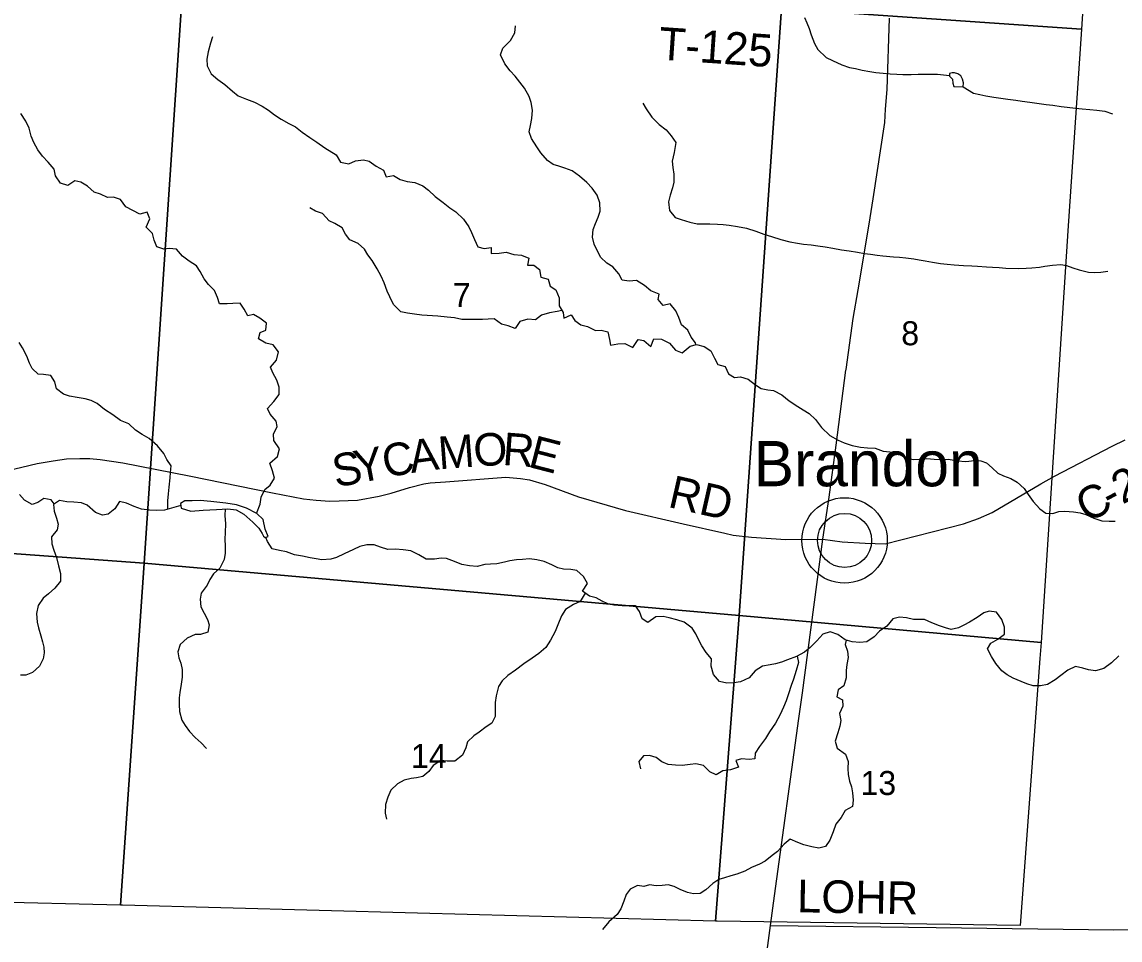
# Model space of a CAD drawing. Extents: x 1759416 to 2214760, y 252598 to 1116833.
# Drawn here: x 1958374 to 1968479, y 838519 to 846970 of the extents above; entities that cross this region are included whole.
import ezdxf

# ---------------------------------------------------------------- set-up
doc = ezdxf.new("R2010")
doc.units = 0
for name, color, linetype in [('GM_X_County_Road', 7, 'Continuous'), ('GM_X_County_Road_Text', 7, 'Continuous'), ('GM_X_Minor_Lake', 7, 'Continuous'), ('GM_X_Minor_River', 7, 'Continuous'), ('GM_X_Section', 7, 'Continuous'), ('GM_X_Section_Text', 7, 'Continuous'), ('GM_X_State_Route', 7, 'Continuous'), ('GM_X_Township_Road', 7, 'Continuous'), ('GM_X_Township_Road_Text', 7, 'Continuous'), ('GM_X_Unincorporated', 7, 'Continuous'), ('GM_X_Unincorporated_Location', 7, 'Continuous'), ('GM_X_Unincorporated_Text', 7, 'Continuous')]:
    doc.layers.add(name, color=color, linetype=linetype)

msp = doc.modelspace()

# ---------------------------------------------------------------- linework, layer by layer
at = {"layer": 'GM_X_County_Road'}
for points in [[(1965744, 842208), (1965923, 842185), (1966133, 842173), (1966317, 842167), (1967040, 842350), (1967176, 842398), (1967302, 842455), (1967751, 842718), (1967877, 842788), (1968408, 843065), (1968526, 843123)], [(1957946, 842771), (1958514, 842905), (1958662, 842931), (1958783, 842949), (1958907, 842953), (1958997, 842953), (1959095, 842943), (1959301, 842913), (1959912, 842791), (1960681, 842635), (1960964, 842579), (1961082, 842567), (1961208, 842559), (1961462, 842569), (1961661, 842605), (1961773, 842633), (1961939, 842686), (1962071, 842718), (1962129, 842726), (1962273, 842738), (1962826, 842780), (1962962, 842768), (1963046, 842754), (1963189, 842712), (1963495, 842600), (1963928, 842474), (1964459, 842349), (1964841, 842263), (1964919, 842247), (1965089, 842227), (1965404, 842205), (1965744, 842208)]]:
    msp.add_lwpolyline(points, dxfattribs=at)
at = {"layer": 'GM_X_Minor_Lake'}
for points in [[(1967034, 846372), (1967038, 846410), (1967029, 846444), (1967013, 846473), (1966987, 846491), (1966957, 846501), (1966935, 846502), (1966909, 846494), (1966909, 846470), (1966937, 846442), (1966940, 846405), (1966950, 846375)], [(1966950, 846375), (1967034, 846372)], [(1960639, 842232), (1960612, 842301), (1960593, 842389), (1960536, 842444), (1960440, 842494), (1960347, 842525), (1960251, 842540), (1960113, 842556), (1960015, 842565), (1959939, 842562), (1959873, 842561), (1959834, 842536), (1959838, 842494), (1959927, 842468), (1960042, 842475), (1960164, 842483), (1960268, 842488), (1960344, 842479), (1960415, 842440), (1960499, 842364), (1960554, 842311), (1960583, 842261)], [(1960583, 842261), (1960597, 842236), (1960611, 842223), (1960639, 842232)]]:
    msp.add_lwpolyline(points, dxfattribs=at)
at = {"layer": 'GM_X_Minor_River'}
for points in [[(1964575, 844001), (1964572, 844016), (1964531, 844069), (1964503, 844132), (1964442, 844183), (1964419, 844249), (1964392, 844312), (1964339, 844375), (1964276, 844359), (1964229, 844414), (1964238, 844464), (1964162, 844495), (1964103, 844544), (1964029, 844591), (1963963, 844584), (1963897, 844593), (1963868, 844650), (1963811, 844717), (1963757, 844751), (1963698, 844806), (1963641, 844923), (1963624, 844990), (1963631, 845058), (1963652, 845114), (1963675, 845172), (1963694, 845228), (1963691, 845304), (1963666, 845376), (1963620, 845441), (1963571, 845492), (1963506, 845549), (1963436, 845600), (1963371, 845625), (1963313, 845642), (1963261, 845659), (1963209, 845695), (1963148, 845764), (1963111, 845821), (1963064, 845896), (1963041, 845958), (1963054, 846018), (1963067, 846082), (1963072, 846157), (1963061, 846229), (1963043, 846285), (1963000, 846360), (1962914, 846470), (1962866, 846520), (1962819, 846585), (1962778, 846666), (1962799, 846730), (1962870, 846799), (1962909, 846869), (1962916, 846935)], [(1965575, 847011), (1965596, 846961), (1965618, 846909), (1965637, 846852), (1965666, 846772), (1965697, 846715), (1965776, 846642), (1965834, 846615), (1965918, 846576), (1965989, 846551), (1966045, 846540), (1966105, 846527), (1966175, 846514), (1966233, 846505), (1966299, 846498), (1966363, 846491), (1966425, 846489), (1966479, 846486), (1966557, 846485), (1966621, 846488), (1966685, 846489), (1966743, 846490), (1966799, 846488), (1966909, 846478)], [(1960126, 846832), (1960110, 846776), (1960086, 846696), (1960076, 846628), (1960077, 846566), (1960114, 846493), (1960175, 846440), (1960241, 846395), (1960312, 846332), (1960363, 846291), (1960439, 846260), (1960513, 846231), (1960584, 846194), (1960644, 846159), (1960699, 846114), (1960759, 846075), (1960830, 846034), (1960890, 846005), (1960953, 845954), (1961023, 845905), (1961086, 845862), (1961161, 845811), (1961265, 845746), (1961304, 845679), (1961382, 845664), (1961442, 845693), (1961516, 845702), (1961570, 845687), (1961632, 845642), (1961701, 845605), (1961726, 845545), (1961794, 845556), (1961854, 845521), (1961918, 845502), (1961988, 845491), (1962063, 845462), (1962115, 845423), (1962176, 845364), (1962249, 845307), (1962311, 845260), (1962368, 845223), (1962436, 845154), (1962485, 845083), (1962512, 845033), (1962537, 844966), (1962570, 844900), (1962628, 844885), (1962692, 844894), (1962692, 844838), (1962764, 844841), (1962830, 844850), (1962900, 844829), (1962972, 844824), (1963037, 844797), (1963026, 844731), (1963084, 844730), (1963138, 844690), (1963149, 844621), (1963215, 844602), (1963236, 844538), (1963287, 844503), (1963319, 844430), (1963318, 844356), (1963353, 844294), (1963360, 844243), (1963429, 844274), (1963462, 844222), (1963517, 844183), (1963579, 844168), (1963653, 844131), (1963703, 844132), (1963765, 844116), (1963782, 844047), (1963789, 843995), (1963857, 844006), (1963923, 844009), (1963995, 843974), (1964044, 844046), (1964096, 844039), (1964161, 843984), (1964190, 844052), (1964260, 844051), (1964334, 844014), (1964389, 843949), (1964451, 843924), (1964522, 843987), (1964582, 844002), (1964652, 843981), (1964713, 843942), (1964748, 843876), (1964779, 843817), (1964845, 843798), (1964876, 843732), (1964932, 843697), (1964986, 843702), (1965058, 843681), (1965125, 843630), (1965177, 843597), (1965239, 843584), (1965291, 843576), (1965366, 843538)], [(1967034, 846372), (1967129, 846315), (1967189, 846302), (1967245, 846291), (1967317, 846278), (1967448, 846260), (1967520, 846249), (1967578, 846240), (1967648, 846231), (1967714, 846222), (1967800, 846211), (1967860, 846204), (1967938, 846193), (1967992, 846187), (1968070, 846176), (1968132, 846169), (1968200, 846164), (1968264, 846157), (1968340, 846148), (1968411, 846125)], [(1964087, 846221), (1964119, 846171), (1964170, 846092), (1964237, 846025), (1964302, 845976), (1964349, 845921), (1964391, 845860), (1964377, 845768), (1964356, 845690), (1964364, 845630), (1964373, 845570), (1964374, 845495), (1964361, 845443), (1964340, 845377), (1964325, 845313), (1964334, 845233), (1964385, 845170), (1964439, 845151), (1964521, 845128), (1964589, 845113), (1964703, 845112), (1964775, 845109), (1964827, 845104), (1964881, 845099), (1964959, 845088), (1965043, 845071), (1965126, 845044), (1965200, 845015), (1965272, 844994), (1965359, 844967), (1965441, 844947), (1965511, 844934), (1965565, 844924), (1965637, 844917), (1965697, 844908), (1965765, 844899), (1965837, 844888), (1965915, 844873), (1965986, 844862), (1966062, 844851), (1966128, 844840), (1966182, 844831), (1966244, 844822), (1966296, 844816), (1966394, 844808), (1966450, 844805), (1966508, 844799), (1966580, 844788), (1966632, 844779), (1966686, 844772), (1966754, 844759), (1966828, 844748), (1966888, 844741), (1966954, 844734), (1967040, 844729), (1967114, 844724), (1967168, 844722), (1967250, 844716), (1967306, 844712), (1967368, 844709), (1967428, 844704), (1967546, 844702), (1967616, 844704), (1967668, 844707), (1967738, 844714), (1967788, 844721), (1967858, 844732), (1967934, 844737), (1967986, 844727), (1968044, 844708), (1968104, 844687), (1968190, 844666), (1968242, 844663), (1968302, 844668), (1968366, 844675)], [(1960532, 842446), (1960567, 842530), (1960574, 842596), (1960609, 842666), (1960659, 842707), (1960698, 842771), (1960679, 842839), (1960654, 842910), (1960725, 842971), (1960744, 843039), (1960691, 843116), (1960688, 843176), (1960721, 843246), (1960713, 843296), (1960658, 843361), (1960633, 843412), (1960692, 843477), (1960741, 843540), (1960741, 843607), (1960720, 843673), (1960683, 843740), (1960662, 843792), (1960717, 843858), (1960736, 843932), (1960687, 843997), (1960619, 844013), (1960551, 844052), (1960566, 844110), (1960618, 844132), (1960625, 844196), (1960562, 844243), (1960506, 844278), (1960454, 844264), (1960419, 844325), (1960382, 844380), (1960313, 844377), (1960263, 844375), (1960193, 844376), (1960172, 844435), (1960147, 844499), (1960092, 844554), (1960052, 844605), (1960013, 844673), (1959980, 844726), (1959914, 844767), (1959851, 844814), (1959796, 844879), (1959730, 844884), (1959680, 844879), (1959614, 844899), (1959591, 844962), (1959576, 845024), (1959518, 845081), (1959551, 845159), (1959526, 845218), (1959460, 845200), (1959394, 845233), (1959329, 845268), (1959282, 845337), (1959216, 845358), (1959162, 845355), (1959098, 845386), (1959038, 845403), (1958977, 845458), (1958917, 845494), (1958860, 845507), (1958795, 845466), (1958727, 845487), (1958684, 845554), (1958671, 845614), (1958616, 845679), (1958562, 845736), (1958519, 845793), (1958482, 845859), (1958459, 845920), (1958440, 845992), (1958409, 846057), (1958363, 846128)], [(1963341, 844314), (1963299, 844306), (1963229, 844293), (1963156, 844270), (1963100, 844227), (1963028, 844234), (1962955, 844213), (1962914, 844147), (1962849, 844174), (1962787, 844187), (1962719, 844236), (1962663, 844235), (1962611, 844231), (1962547, 844230), (1962479, 844231), (1962421, 844232), (1962353, 844245), (1962287, 844254), (1962201, 844261), (1962053, 844271), (1961985, 844280), (1961922, 844289), (1961860, 844302), (1961794, 844369), (1961759, 844439), (1961736, 844492), (1961707, 844570), (1961680, 844631), (1961643, 844698), (1961598, 844774), (1961558, 844827), (1961525, 844878), (1961468, 844931), (1961392, 844964), (1961351, 845018), (1961322, 845075), (1961254, 845114), (1961202, 845139), (1961139, 845206), (1961075, 845229), (1961024, 845258)], [(1959716, 842486), (1959715, 842561), (1959723, 842626), (1959730, 842688), (1959737, 842774), (1959742, 842824), (1959747, 842884), (1959706, 842943), (1959680, 842999), (1959621, 843068), (1959546, 843135), (1959479, 843172), (1959419, 843213), (1959358, 843272), (1959280, 843301), (1959211, 843352), (1959133, 843404), (1959066, 843457), (1959012, 843486), (1958957, 843500), (1958883, 843513), (1958811, 843526), (1958757, 843543), (1958692, 843594), (1958677, 843658), (1958641, 843715), (1958573, 843726), (1958523, 843729), (1958468, 843780), (1958443, 843830), (1958419, 843895), (1958378, 843969), (1958349, 844020)], [(1965366, 843538), (1965433, 843481), (1965513, 843430), (1965564, 843399), (1965618, 843365), (1965675, 843310), (1965732, 843237), (1965809, 843163), (1965885, 843120), (1965939, 843097), (1966014, 843070), (1966090, 843055), (1966156, 843050), (1966226, 843047), (1966298, 843020), (1966362, 843012), (1966438, 842994), (1966509, 842957), (1966579, 842942), (1966629, 842944), (1966701, 842953), (1966769, 842946), (1966847, 842941), (1966901, 842944), (1966983, 842929), (1967061, 842924), (1967141, 842933), (1967197, 842930), (1967251, 842911), (1967303, 842866), (1967354, 842818), (1967408, 842793), (1967473, 842766), (1967533, 842735), (1967596, 842676), (1967634, 842621), (1967681, 842556), (1967742, 842489), (1967795, 842449), (1967861, 842446), (1967916, 842463), (1967972, 842466), (1968050, 842461), (1968112, 842452), (1968164, 842436), (1968239, 842403), (1968311, 842378), (1968379, 842375), (1968435, 842376)], [(1958669, 842533), (1958644, 842572), (1958574, 842583), (1958519, 842545), (1958467, 842528), (1958396, 842567), (1958352, 842620)], [(1959836, 842518), (1959685, 842476), (1959613, 842473), (1959549, 842475), (1959475, 842486), (1959406, 842509), (1959336, 842540), (1959270, 842557), (1959227, 842488), (1959166, 842438), (1959116, 842429), (1959051, 842454), (1958973, 842523), (1958922, 842542), (1958852, 842551), (1958786, 842552), (1958718, 842565), (1958663, 842529), (1958670, 842467), (1958692, 842401), (1958707, 842348), (1958698, 842296), (1958647, 842229), (1958650, 842165), (1958668, 842108), (1958691, 842040), (1958710, 841963), (1958729, 841893), (1958728, 841821), (1958677, 841757), (1958618, 841706), (1958568, 841666), (1958523, 841597), (1958508, 841525), (1958515, 841444), (1958526, 841392), (1958549, 841318), (1958562, 841265), (1958574, 841215), (1958577, 841163), (1958568, 841107), (1958535, 841041), (1958472, 840982), (1958410, 840958), (1958360, 840957)], [(1960244, 842487), (1960241, 842428), (1960246, 842350), (1960243, 842270), (1960240, 842209), (1960243, 842145), (1960245, 842081), (1960236, 842023), (1960195, 841941), (1960138, 841890), (1960103, 841838), (1960078, 841784), (1960023, 841713), (1960013, 841657), (1960020, 841585), (1960051, 841528), (1960080, 841471), (1960098, 841421), (1960085, 841353), (1960018, 841332), (1959968, 841331), (1959894, 841299), (1959829, 841240), (1959808, 841172), (1959817, 841118), (1959837, 841068), (1959848, 841009), (1959849, 840939), (1959840, 840875), (1959827, 840797), (1959822, 840747), (1959821, 840687), (1959825, 840622), (1959845, 840544), (1959875, 840493), (1959916, 840437), (1959969, 840384), (1960023, 840333), (1960072, 840282)], [(1963112, 842020), (1963046, 842027), (1962980, 842022), (1962926, 842019), (1962864, 842010), (1962813, 841998), (1962745, 841983), (1962685, 841978), (1962633, 841975), (1962563, 841958), (1962493, 841962), (1962423, 841975), (1962353, 842004), (1962281, 842032), (1962231, 842034), (1962171, 842025), (1962093, 842024), (1962026, 842065), (1961954, 842102), (1961882, 842111), (1961812, 842118), (1961740, 842115), (1961672, 842134), (1961615, 842157), (1961549, 842158), (1961484, 842141), (1961424, 842113), (1961339, 842074), (1961269, 842041), (1961215, 842026), (1961132, 842019), (1961080, 842028), (1961025, 842038), (1960957, 842051), (1960881, 842066), (1960807, 842093), (1960743, 842104), (1960675, 842119), (1960632, 842189), (1960618, 842225)], [(1968468, 841136), (1968399, 841071), (1968329, 841019), (1968254, 840996), (1968188, 841007), (1968137, 841022), (1968069, 841037), (1967998, 841002), (1967935, 840954), (1967883, 840915), (1967810, 840870), (1967748, 840859), (1967680, 840860), (1967620, 840876), (1967568, 840899), (1967495, 840930), (1967441, 840959), (1967390, 840998), (1967336, 841065), (1967297, 841130), (1967260, 841198), (1967289, 841252), (1967355, 841289), (1967416, 841333), (1967415, 841399), (1967390, 841471), (1967343, 841536), (1967275, 841547), (1967225, 841532), (1967164, 841488), (1967095, 841445), (1967043, 841416), (1966993, 841394), (1966924, 841377), (1966873, 841394), (1966817, 841411), (1966747, 841438), (1966679, 841469), (1966577, 841470), (1966515, 841485), (1966451, 841490), (1966389, 841475), (1966332, 841409), (1966266, 841362), (1966215, 841311), (1966150, 841265), (1966084, 841258), (1966014, 841265), (1965950, 841282), (1965883, 841331), (1965813, 841356), (1965745, 841333), (1965690, 841274), (1965627, 841212), (1965576, 841169), (1965502, 841128), (1965419, 841097), (1965363, 841077), (1965309, 841062), (1965259, 841051), (1965188, 841040), (1965120, 840996), (1965065, 840933), (1964986, 840896), (1964924, 840885), (1964860, 840882), (1964792, 840899), (1964737, 840963), (1964716, 841040), (1964719, 841106), (1964670, 841167), (1964630, 841228), (1964599, 841284), (1964574, 841339), (1964543, 841389), (1964467, 841444), (1964399, 841465), (1964330, 841486), (1964274, 841497), (1964208, 841494), (1964133, 841443), (1964081, 841476), (1964056, 841542), (1964021, 841595), (1963949, 841594), (1963897, 841595), (1963821, 841600), (1963765, 841614), (1963713, 841637), (1963658, 841668), (1963596, 841685), (1963532, 841730), (1963577, 841801), (1963542, 841866), (1963481, 841919), (1963425, 841930), (1963357, 841933), (1963305, 841946), (1963251, 841974), (1963180, 842003), (1963112, 842020)], [(1963556, 841713), (1963511, 841636), (1963451, 841607), (1963376, 841563), (1963339, 841504), (1963304, 841420), (1963281, 841360), (1963238, 841279), (1963195, 841213), (1963130, 841158), (1963068, 841114), (1962991, 841061), (1962916, 841004), (1962845, 840955), (1962793, 840905), (1962758, 840854), (1962739, 840768), (1962730, 840704), (1962729, 840634), (1962730, 840577), (1962699, 840514), (1962645, 840482), (1962582, 840431), (1962532, 840400), (1962475, 840342), (1962458, 840288), (1962427, 840222), (1962358, 840165), (1962286, 840164), (1962230, 840171), (1962158, 840124), (1962119, 840070), (1962062, 840025), (1962006, 840013), (1961956, 840006), (1961890, 839989), (1961829, 839958), (1961768, 839898), (1961741, 839835), (1961718, 839765), (1961715, 839688), (1961729, 839632)], [(1965960, 841279), (1965950, 841240), (1965971, 841178), (1965978, 841121), (1965965, 841055), (1965960, 840999), (1965958, 840933), (1965937, 840859), (1965886, 840822), (1965873, 840758), (1965925, 840729), (1965928, 840673), (1965897, 840605), (1965910, 840541), (1965900, 840489), (1965883, 840427), (1965858, 840351), (1965877, 840286), (1965952, 840231), (1965977, 840163), (1965974, 840098), (1965976, 840044), (1965989, 839982), (1966008, 839929), (1966017, 839875), (1966022, 839805), (1966016, 839747), (1965949, 839710), (1965912, 839646), (1965865, 839584), (1965840, 839515), (1965809, 839437), (1965769, 839381), (1965708, 839366), (1965644, 839377), (1965569, 839394), (1965515, 839417), (1965443, 839448), (1965388, 839400), (1965328, 839333), (1965277, 839296), (1965212, 839244), (1965160, 839217), (1965087, 839186), (1965027, 839154), (1964954, 839125), (1964898, 839110), (1964838, 839093), (1964788, 839077), (1964733, 839040), (1964666, 838981), (1964614, 838947), (1964554, 838944), (1964500, 838957), (1964430, 838984), (1964376, 839011), (1964321, 839028), (1964264, 839022), (1964210, 839017), (1964148, 839028), (1964098, 839011), (1964038, 839021), (1963970, 838988), (1963935, 838937), (1963914, 838877), (1963885, 838807), (1963851, 838753), (1963776, 838686), (1963717, 838615)], [(1965509, 841132), (1965519, 841075), (1965498, 841001), (1965473, 840919), (1965452, 840862), (1965429, 840784), (1965408, 840720), (1965383, 840664), (1965351, 840594), (1965307, 840515), (1965254, 840435), (1965217, 840375), (1965162, 840300), (1965122, 840240), (1965117, 840186), (1965065, 840181), (1964995, 840186), (1964943, 840172), (1964968, 840110), (1964895, 840087), (1964825, 840076), (1964763, 840039), (1964705, 840067), (1964646, 840126), (1964576, 840141), (1964524, 840134), (1964450, 840127), (1964389, 840130), (1964320, 840135), (1964262, 840160), (1964210, 840198), (1964148, 840217), (1964094, 840214), (1964050, 840162), (1964067, 840094)]]:
    msp.add_lwpolyline(points, dxfattribs=at)
at = {"layer": 'GM_X_Section'}
for points in [[(1965691, 851865), (1968437, 851701), (1968218, 848385), (1968124, 846904), (1965363, 847094)], [(1954507, 847691), (1954521, 847897), (1959866, 847492), (1959498, 841988), (1954169, 842378)], [(1959866, 847492), (1965363, 847094), (1964974, 841505), (1959498, 841988)], [(1965363, 847094), (1968124, 846904), (1968000, 845047), (1967752, 841259), (1964974, 841505)], [(1954151, 842124), (1954169, 842378), (1959498, 841988), (1959280, 838840), (1956743, 838902), (1953941, 838971), (1953967, 839393)], [(1964974, 841505), (1964756, 838694), (1962015, 838767), (1959299, 838839), (1959280, 838840), (1959498, 841988)], [(1967752, 841259), (1967741, 841109), (1967560, 838652), (1964773, 838694), (1964756, 838694), (1964974, 841505)]]:
    msp.add_lwpolyline(points, close=True, dxfattribs=at)
at = {"layer": 'GM_X_State_Route'}
for points in [[(1965958, 843772), (1966024, 844239), (1966069, 844504), (1966170, 845110), (1966208, 845342), (1966314, 846044), (1966322, 846168), (1966336, 846349), (1966359, 847005)], [(1965524, 840559), (1965556, 840794), (1965744, 842208), (1965803, 842597), (1965866, 843074), (1965957, 843764), (1965958, 843772)], [(1963814, 825573), (1963821, 825713), (1963924, 826957), (1964062, 828200), (1964292, 830227), (1964312, 830423), (1964417, 831426), (1964494, 832162), (1964673, 833738), (1964788, 834760), (1964949, 836170), (1965039, 836976), (1965146, 837776), (1965262, 838653), (1965298, 838925), (1965524, 840559)]]:
    msp.add_lwpolyline(points, dxfattribs=at)
at = {"layer": 'GM_X_Township_Road'}
msp.add_lwpolyline([(1965262, 838653), (1966787, 838635), (1968421, 838613), (1969027, 838617), (1970741, 838602), (1971457, 838602)], dxfattribs=at)
at = {"layer": 'GM_X_Unincorporated'}
for radius in [393, 249]:
    msp.add_circle((1965944, 842197), radius, dxfattribs=at)
at = {"layer": 'GM_X_Unincorporated_Location'}
msp.add_line((1965944, 842197), (1965944, 842197), dxfattribs=at)

# ---------------------------------------------------------------- texts
at = {"layer": 'GM_X_County_Road_Text'}
for s, rotation, p in [('O', 3.7293, (1962538, 842876)), ('R', 355.6911, (1962790, 842893)), ('C', 10.7335, (1961719, 842772)), ('A', 7.6799, (1961957, 842817)), ('M', 4.3518, (1962214, 842852)), ('E', 345.5023, (1963022, 842877)), ('S', 10.7536, (1961261, 842684)), ('Y', 10.7539, (1961460, 842722)), ('RD', 347.2628, (1964309, 842507)), ('2', 27.5007, (1968501, 842526)), ('C', 27.8236, (1968175, 842354)), ('-', 27.7974, (1968393, 842469))]:
    msp.add_text(s, height=300, rotation=rotation, dxfattribs=at).set_placement(p)
at = {"layer": 'GM_X_Section_Text'}
for s, p in [('7', (1962339, 844345)), ('8', (1966466, 843994)), ('14', (1961954, 840102)), ('13', (1966090, 839854))]:
    msp.add_text(s, height=221, rotation=0, dxfattribs=at).set_placement(p)
at = {"layer": 'GM_X_Township_Road_Text'}
for s, rotation, p in [('T-125', 356.0741, (1964226, 846625)), ('LOHR', 358.9901, (1965505, 838775))]:
    msp.add_text(s, height=300, rotation=rotation, dxfattribs=at).set_placement(p)
at = {"layer": 'GM_X_Unincorporated_Text'}
msp.add_text('Brandon', height=417, rotation=0, dxfattribs=at).set_placement((1965107, 842696))

doc.saveas('drawing.dxf')
